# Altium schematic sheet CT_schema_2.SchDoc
size 278 x 262 mm
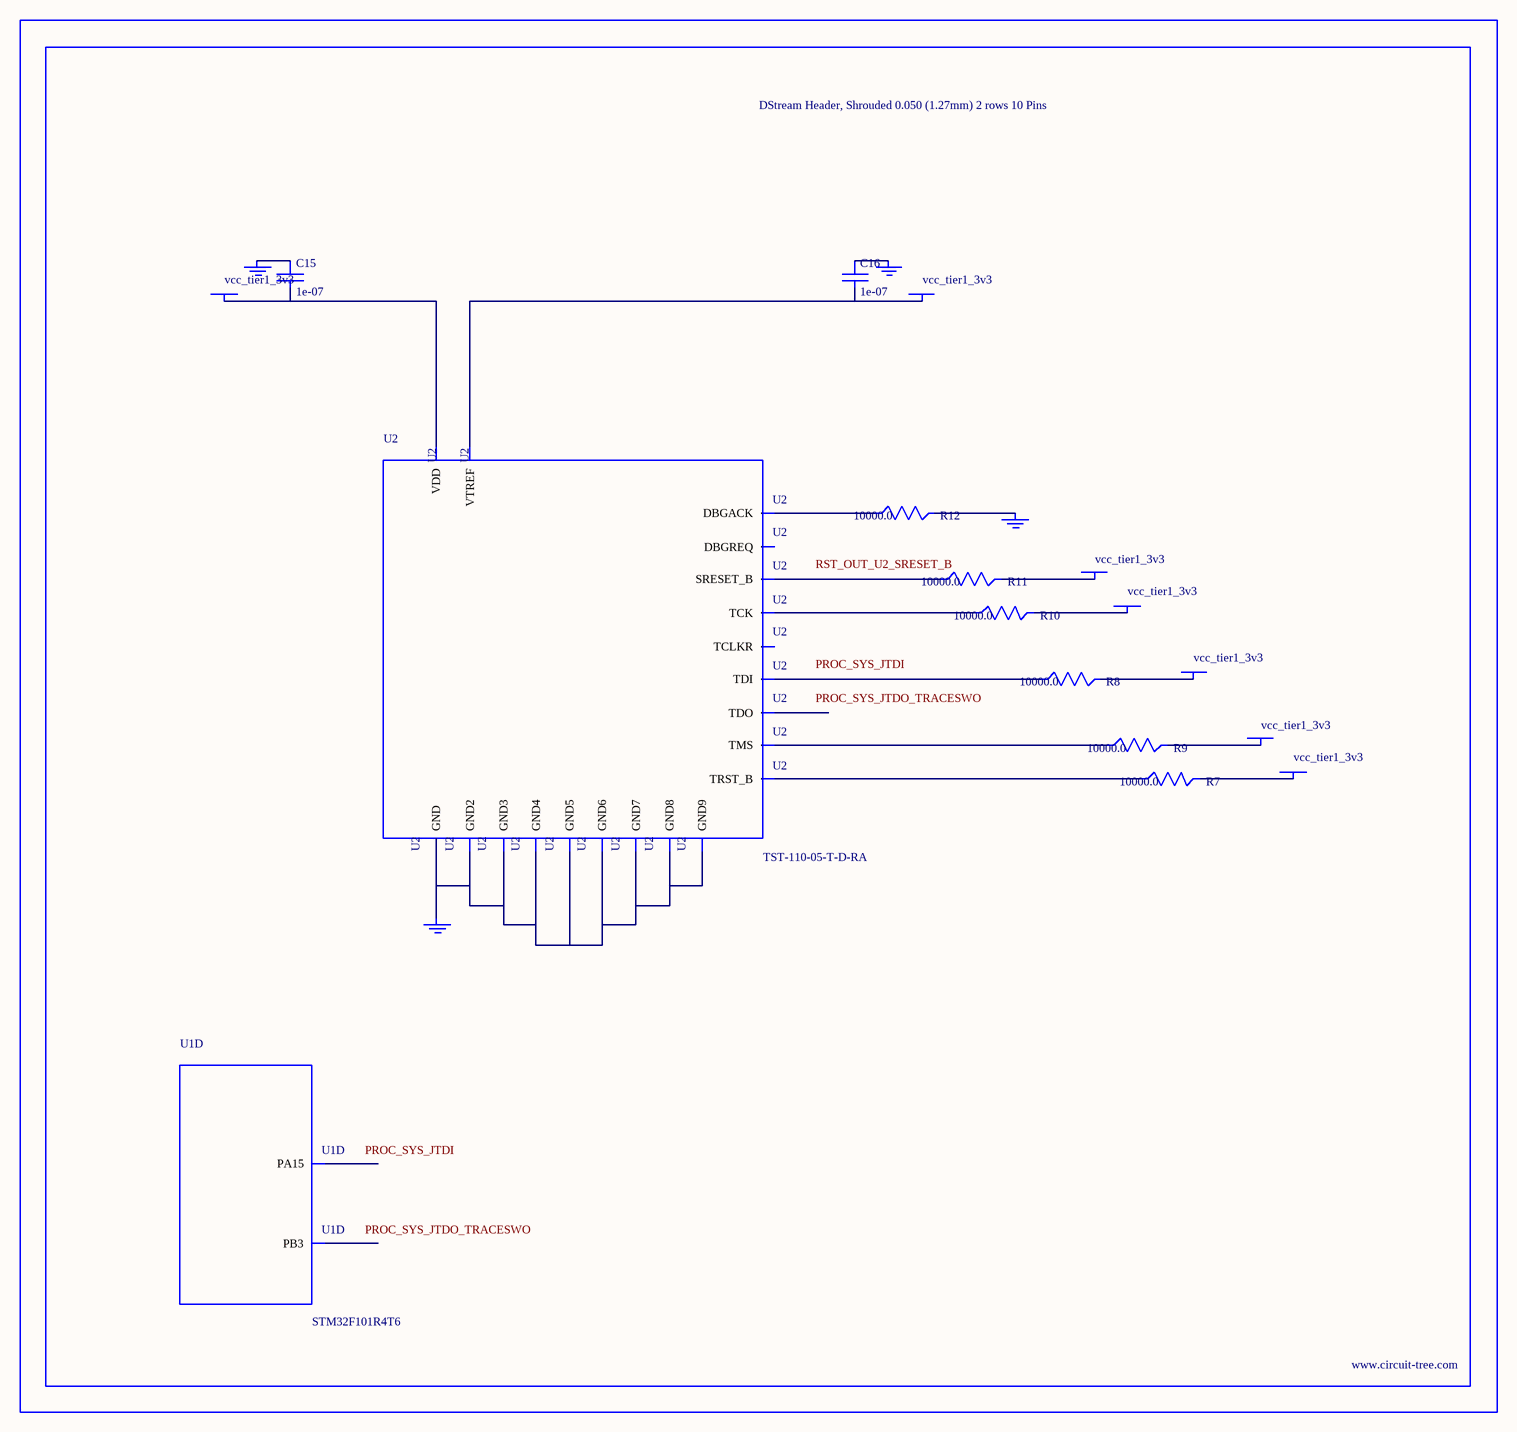
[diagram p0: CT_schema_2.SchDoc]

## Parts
BORDER1  (no value)
C15  1e-07  [C0402]
C16  1e-07  [C0402]
GND_INSTANCE_1_0  (no value)
GND_INSTANCE_1_1  (no value)
GND_INSTANCE_1_2  (no value)
GND_INSTANCE_1_3  (no value)
POWER_INSTANCE_1_0  vcc_tier1_3v3
POWER_INSTANCE_1_1  vcc_tier1_3v3
POWER_INSTANCE_1_2  vcc_tier1_3v3
POWER_INSTANCE_1_3  vcc_tier1_3v3
POWER_INSTANCE_1_4  vcc_tier1_3v3
POWER_INSTANCE_1_5  vcc_tier1_3v3
POWER_INSTANCE_1_6  vcc_tier1_3v3
R7  10000.0  [R0603]
R8  10000.0  [R0603]
R9  10000.0  [R0603]
R10  10000.0  [R0603]
R11  10000.0  [R0603]
R12  10000.0  [R0603]
U1  STM32F101R4T6  [LQFP64]  (part D of 7)
U2  TST-110-05-T-D-RA  [TST-110-05-T-D-RA]

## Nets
NetC15_1: C15.1 GND_INSTANCE_1_1.0(GND)
NetC15_2: C15.2 POWER_INSTANCE_1_1.0(PWR) U2.2(VDD)
NetC16_1: C16.1 GND_INSTANCE_1_0.0(GND)
NetC16_2: C16.2 POWER_INSTANCE_1_0.0(PWR) U2.1(VTREF)
NetGND_INSTANCE_1_2_0: GND_INSTANCE_1_2.0(GND) R12.2
NetGND_INSTANCE_1_3_0: GND_INSTANCE_1_3.0(GND) U2.4(GND) U2.6(GND2) U2.8(GND3) U2.10(GND4) U2.12(GND5) U2.14(GND6) U2.16(GND7) U2.18(GND8) U2.20(GND9)
NetPOWER_INSTANCE_1_2_0: POWER_INSTANCE_1_2.0(PWR) R7.2
NetPOWER_INSTANCE_1_3_0: POWER_INSTANCE_1_3.0(PWR) R8.2
NetPOWER_INSTANCE_1_4_0: POWER_INSTANCE_1_4.0(PWR) R9.2
NetPOWER_INSTANCE_1_5_0: POWER_INSTANCE_1_5.0(PWR) R10.2
NetPOWER_INSTANCE_1_6_0: POWER_INSTANCE_1_6.0(PWR) R11.2
NetR7_1: R7.1 U2.3(TRST_B)
NetR8_1: R8.1 U2.5(TDI)
NetR9_1: R9.1 U2.7(TMS)
NetR10_1: R10.1 U2.9(TCK)
NetR11_1: R11.1 U2.15(SRESET_B)
NetR12_1: R12.1 U2.19(DBGACK)

Not connected (* = marked no-connect by the designer): U1 50(PA15) 55(PB3); U2 11(TCLKR) 13(TDO) 17(DBGREQ)

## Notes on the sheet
- Labels drawn without touching a wire or pin: PROC_SYS_JTDI, PROC_SYS_JTDO_TRACESWO, RST_OUT_U2_SRESET_B

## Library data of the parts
BORDER1 = BORDER_PAGE1
C15 C16 = C0402C104K3RACTU
GND_INSTANCE_1_0-GND_INSTANCE_1_3 = GND
POWER_INSTANCE_1_0-POWER_INSTANCE_1_6 = PWR
R7-R12 = RC0603JR-0710KL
